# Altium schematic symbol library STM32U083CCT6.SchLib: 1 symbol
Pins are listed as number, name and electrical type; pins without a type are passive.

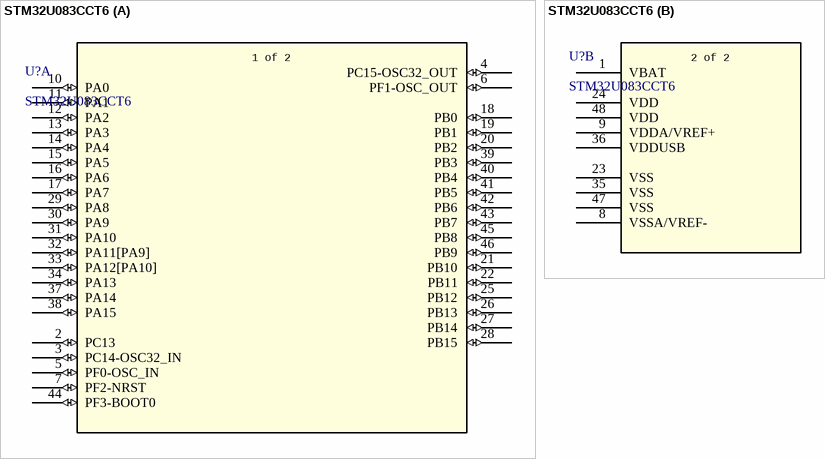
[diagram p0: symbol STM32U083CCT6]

## STM32U083CCT6
designator U?
Ultra-low-power Arm Cortex-M0+ MCU with 256 Kbytes of Flash memory, LCD, USB, AES, 56 MHz CPU; Manufacturer_Name: STMicroelectronics
footprint LQFP48_STM
part A pins: 2 PC13 (io), 3 PC14-OSC32_IN (io), 4 PC15-OSC32_OUT (io), 5 PF0-OSC_IN (io), 6 PF1-OSC_OUT (io), 7 PF2-NRST (io), 10 PA0 (io), 11 PA1 (io), 12 PA2 (io), 13 PA3 (io), 14 PA4 (io), 15 PA5 (io), 16 PA6 (io), 17 PA7 (io), 18 PB0 (io), 19 PB1 (io), 20 PB2 (io), 21 PB10 (io), 22 PB11 (io), 25 PB12 (io), 26 PB13 (io), 27 PB14 (io), 28 PB15 (io), 29 PA8 (io), 30 PA9 (io), 31 PA10 (io), 32 PA11[PA9] (io), 33 PA12[PA10] (io), 34 PA13 (io), 37 PA14 (io), 38 PA15 (io), 39 PB3 (io), 40 PB4 (io), 41 PB5 (io), 42 PB6 (io), 43 PB7 (io), 44 PF3-BOOT0 (io), 45 PB8 (io), 46 PB9 (io)
part B pins: 1 VBAT (power), 8 VSSA/VREF- (power), 9 VDDA/VREF+ (power), 23 VSS (power), 24 VDD (power), 35 VSS (power), 36 VDDUSB (power), 47 VSS (power), 48 VDD (power)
